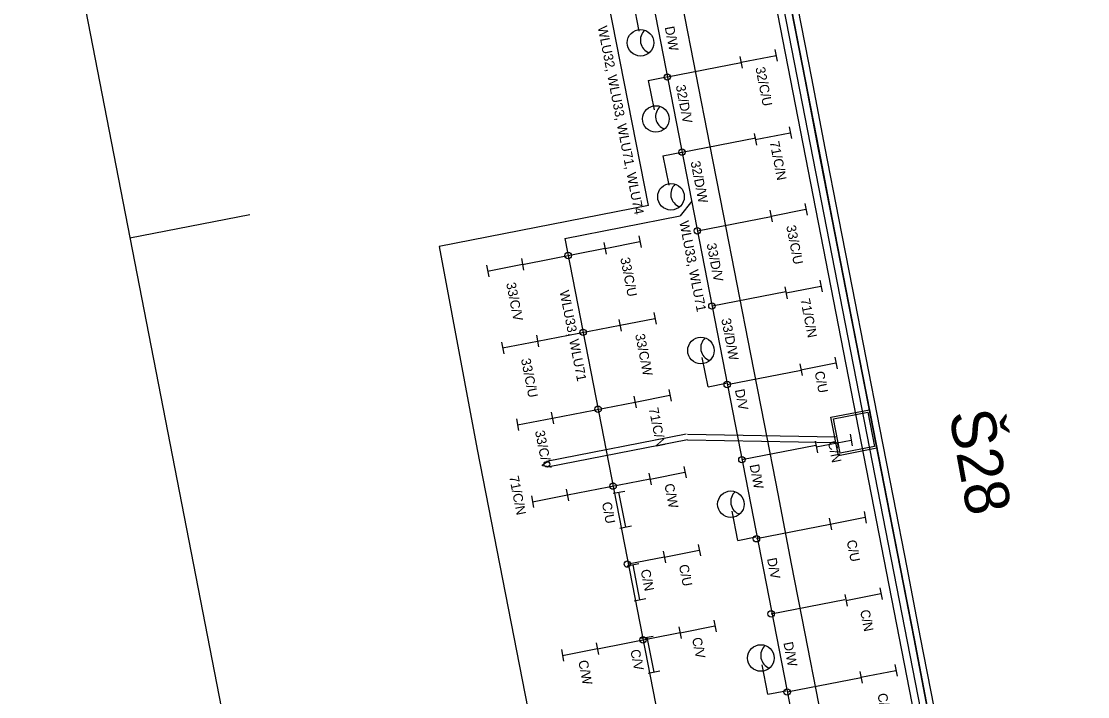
# Model space of a CAD drawing. Extents: x -545258 to -544992, y -1122311 to -1121664.
# Drawn here: x -545221.17 to -545191.21, y -1121911.45 to -1121892.48 of the extents above; entities that cross this region are included whole.
import ezdxf

# ---------------------------------------------------------------- set-up
doc = ezdxf.new("R2010")
doc.units = 0
for name, color, linetype in [('SO18-15-04', 7, 'Continuous'), ('SO18-15-08', 7, 'Continuous'), ('SO18-15-08_def', 7, 'Continuous'), ('SO18-16-02', 7, 'Continuous'), ('SO18-16-03', 7, 'Continuous'), ('so180605', 7, 'Continuous'), ('Vrstva 10', 7, 'Continuous')]:
    doc.layers.add(name, color=color, linetype=linetype)

msp = doc.modelspace()

# ---------------------------------------------------------------- linework, layer by layer
at = {"layer": 'SO18-15-04'}
for centre in [(-545203.02, -1121894.044), (-545202.609, -1121896.154), (-545202.178, -1121898.365), (-545205.807, -1121899.057), (-545201.767, -1121900.475), (-545205.387, -1121901.216), (-545201.337, -1121902.681), (-545204.966, -1121903.375), (-545200.925, -1121904.792), (-545204.545, -1121905.535), (-545200.516, -1121907.014), (-545204.143, -1121907.725), (-545200.105, -1121909.124), (-545203.703, -1121909.854), (-545199.653, -1121911.319)]:
    msp.add_circle(centre, 0.09, dxfattribs=at)
at = {"layer": 'SO18-15-08_def'}
for p, q in [((-545198.422, -1121903.602), (-545197.343, -1121903.392)), ((-545198.212, -1121904.682), (-545198.422, -1121903.602)), ((-545198.355, -1121903.647), (-545197.388, -1121903.459)), ((-545197.388, -1121903.459), (-545197.2, -1121904.426)), ((-545197.343, -1121903.392), (-545197.132, -1121904.471)), ((-545198.167, -1121904.614), (-545198.355, -1121903.647)), ((-545202.489, -1121904.076), (-545206.417, -1121904.842)), ((-545202.455, -1121904.073), (-545198.29, -1121904.154)), ((-545202.458, -1121904.233), (-545206.386, -1121904.999)), ((-545202.458, -1121904.233), (-545198.293, -1121904.314)), ((-545197.132, -1121904.471), (-545198.212, -1121904.682)), ((-545197.2, -1121904.426), (-545198.167, -1121904.614))]:
    msp.add_line(p, q, dxfattribs=at)
for points in [[(-545216.425, -1121805.557), (-545199.926, -1121890.192), (-545199.543, -1121892.155), (-545199.161, -1121894.118), (-545198.778, -1121896.081), (-545198.395, -1121898.044), (-545198.013, -1121900.008), (-545197.63, -1121901.971), (-545197.247, -1121903.934), (-545196.865, -1121905.897), (-545196.482, -1121907.86), (-545196.099, -1121909.823), (-545195.717, -1121911.786), (-545195.334, -1121913.749), (-545194.951, -1121915.712), (-545194.569, -1121917.675), (-545194.186, -1121919.638), (-545193.803, -1121921.601), (-545193.421, -1121923.564), (-545193.038, -1121925.527), (-545192.841, -1121926.538), (-545192.841, -1121926.538)], [(-545206.25, -1121859.831), (-545193.813, -1121923.641), (-545193.431, -1121925.604), (-545193.234, -1121926.608)]]:
    msp.add_lwpolyline(points, dxfattribs=at)
msp.add_circle((-545206.404, -1121904.922), 0.08, dxfattribs=at)
at = {"layer": 'SO18-16-02'}
for points in [[(-545203.55, -1121897.655), (-545204.006, -1121895.32), (-545211.097, -1121859.276), (-545210.828, -1121859.191), (-545213.136, -1121847.58), (-545213.447, -1121847.636), (-545218.7, -1121820.501), (-545218.434, -1121820.401), (-545220.002, -1121812.223), (-545220.322, -1121812.224), (-545225.746, -1121784.731), (-545225.44, -1121784.622), (-545227.044, -1121776.44), (-545227.334, -1121776.447), (-545232.615, -1121749.298), (-545232.32, -1121749.236), (-545234.53, -1121737.665), (-545234.868, -1121737.675), (-545236.659, -1121728.803)], [(-545191.871, -1121931.413), (-545192.253, -1121929.45), (-545192.636, -1121927.486), (-545193.019, -1121925.523), (-545193.401, -1121923.56), (-545193.784, -1121921.597), (-545194.167, -1121919.634), (-545194.549, -1121917.671), (-545194.932, -1121915.708), (-545195.315, -1121913.745), (-545195.697, -1121911.782), (-545196.08, -1121909.819), (-545196.462, -1121907.856), (-545196.845, -1121905.893), (-545197.228, -1121903.93), (-545197.61, -1121901.967), (-545197.993, -1121900.004), (-545198.376, -1121898.041), (-545198.758, -1121896.078), (-545199.141, -1121894.115), (-545199.524, -1121892.152), (-545199.906, -1121890.189), (-545201.881, -1121880.06)], [(-545191.694, -1121931.378), (-545192.077, -1121929.415), (-545192.459, -1121927.452), (-545192.842, -1121925.489), (-545193.225, -1121923.526), (-545193.607, -1121921.563), (-545193.99, -1121919.6), (-545194.372, -1121917.637), (-545194.755, -1121915.674), (-545195.138, -1121913.711), (-545195.52, -1121911.748), (-545195.903, -1121909.785), (-545196.286, -1121907.822), (-545196.668, -1121905.858), (-545197.051, -1121903.895), (-545197.434, -1121901.932), (-545197.816, -1121899.969), (-545198.199, -1121898.006), (-545198.582, -1121896.043), (-545198.964, -1121894.08), (-545199.347, -1121892.117), (-545199.73, -1121890.154), (-545201.704, -1121880.026)], [(-545202.599, -1121892.01), (-545202.216, -1121893.972), (-545201.833, -1121895.936), (-545201.451, -1121897.898), (-545201.068, -1121899.862), (-545200.685, -1121901.825), (-545200.303, -1121903.788), (-545199.92, -1121905.751), (-545199.537, -1121907.714), (-545199.155, -1121909.677), (-545198.772, -1121911.64), (-545198.389, -1121913.603), (-545198.007, -1121915.566), (-545197.624, -1121917.529), (-545197.241, -1121919.492), (-545196.859, -1121921.455), (-545196.476, -1121923.418), (-545196.093, -1121925.381), (-545195.711, -1121927.344), (-545195.328, -1121929.307), (-545194.945, -1121931.27)]]:
    msp.add_lwpolyline(points, dxfattribs=at)
at = {"layer": 'SO18-16-03'}
msp.add_lwpolyline([(-545203.55, -1121897.655), (-545209.426, -1121898.809), (-545208.358, -1121904.507), (-545203.934, -1121927.17), (-545203.066, -1121927.008), (-545201.304, -1121935.983), (-545201.844, -1121936.082), (-545196.986, -1121960.894)], dxfattribs=at)
at = {"layer": 'so180605'}
for p, q in [((-545203.983, -1121891.937), (-545203.823, -1121892.759)), ((-545200.949, -1121893.63), (-545199.967, -1121893.439)), ((-545199.998, -1121893.276), (-545199.934, -1121893.601)), ((-545200.98, -1121893.464), (-545200.916, -1121893.793)), ((-545203.554, -1121894.14), (-545203.394, -1121894.962)), ((-545199.598, -1121895.446), (-545199.535, -1121895.772)), ((-545200.58, -1121895.635), (-545200.516, -1121895.963)), ((-545200.549, -1121895.801), (-545199.568, -1121895.609)), ((-545203.142, -1121896.256), (-545202.981, -1121897.078)), ((-545199.155, -1121897.597), (-545199.092, -1121897.923)), ((-545200.137, -1121897.785), (-545200.073, -1121898.114)), ((-545200.106, -1121897.952), (-545199.125, -1121897.76)), ((-545203.818, -1121898.503), (-545203.754, -1121898.829)), ((-545204.8, -1121898.692), (-545204.736, -1121899.02)), ((-545204.769, -1121898.858), (-545203.788, -1121898.666)), ((-545208.103, -1121899.329), (-545208.039, -1121899.657)), ((-545208.072, -1121899.495), (-545207.09, -1121899.303)), ((-545207.121, -1121899.14), (-545207.057, -1121899.466)), ((-545199.717, -1121899.942), (-545199.653, -1121900.271)), ((-545199.686, -1121900.108), (-545198.704, -1121899.917)), ((-545198.735, -1121899.754), (-545198.671, -1121900.079)), ((-545204.379, -1121900.851), (-545204.315, -1121901.179)), ((-545204.348, -1121901.017), (-545203.367, -1121900.826)), ((-545203.397, -1121900.662), (-545203.334, -1121900.988)), ((-545207.682, -1121901.488), (-545207.618, -1121901.816)), ((-545207.651, -1121901.654), (-545206.67, -1121901.463)), ((-545206.7, -1121901.299), (-545206.636, -1121901.625)), ((-545201.877, -1121902.744), (-545202.037, -1121901.922)), ((-545199.296, -1121902.102), (-545199.232, -1121902.43)), ((-545199.265, -1121902.268), (-545198.283, -1121902.076)), ((-545198.314, -1121901.913), (-545198.25, -1121902.239)), ((-545203.958, -1121903.01), (-545203.894, -1121903.339)), ((-545203.927, -1121903.177), (-545202.946, -1121902.985)), ((-545202.976, -1121902.822), (-545202.913, -1121903.148)), ((-545207.23, -1121903.813), (-545206.249, -1121903.622)), ((-545206.279, -1121903.459), (-545206.216, -1121903.784)), ((-545207.261, -1121903.647), (-545207.197, -1121903.976)), ((-545197.886, -1121904.079), (-545197.823, -1121904.405)), ((-545198.868, -1121904.268), (-545198.804, -1121904.596)), ((-545198.837, -1121904.434), (-545197.856, -1121904.242)), ((-545202.555, -1121904.981), (-545202.492, -1121905.307)), ((-545203.537, -1121905.17), (-545203.473, -1121905.498)), ((-545203.506, -1121905.336), (-545202.525, -1121905.145)), ((-545205.858, -1121905.618), (-545205.795, -1121905.944)), ((-545204.542, -1121905.737), (-545204.216, -1121905.674)), ((-545204.187, -1121906.688), (-545204.378, -1121905.707)), ((-545206.84, -1121905.807), (-545206.776, -1121906.135)), ((-545206.809, -1121905.973), (-545205.828, -1121905.781)), ((-545201.035, -1121907.063), (-545201.195, -1121906.24)), ((-545197.493, -1121906.246), (-545197.43, -1121906.571)), ((-545198.475, -1121906.434), (-545198.411, -1121906.763)), ((-545198.445, -1121906.6), (-545197.463, -1121906.409)), ((-545204.353, -1121906.719), (-545204.024, -1121906.655)), ((-545202.153, -1121907.172), (-545202.09, -1121907.497)), ((-545203.135, -1121907.36), (-545203.071, -1121907.689)), ((-545203.105, -1121907.526), (-545202.123, -1121907.335)), ((-545204.144, -1121907.775), (-545203.818, -1121907.712)), ((-545203.789, -1121908.726), (-545203.981, -1121907.745)), ((-545197.051, -1121908.391), (-545196.988, -1121908.717)), ((-545203.956, -1121908.757), (-545203.627, -1121908.693)), ((-545198.033, -1121908.58), (-545197.969, -1121908.908)), ((-545198.002, -1121908.746), (-545197.021, -1121908.554)), ((-545201.713, -1121909.3), (-545201.65, -1121909.626)), ((-545202.695, -1121909.488), (-545202.631, -1121909.817)), ((-545202.664, -1121909.655), (-545201.683, -1121909.463)), ((-545203.747, -1121909.81), (-545203.421, -1121909.747)), ((-545203.392, -1121910.761), (-545203.584, -1121909.78)), ((-545205.998, -1121910.125), (-545205.934, -1121910.454)), ((-545205.967, -1121910.292), (-545204.986, -1121910.1)), ((-545205.016, -1121909.937), (-545204.953, -1121910.263)), ((-545203.558, -1121910.792), (-545203.23, -1121910.728)), ((-545200.193, -1121911.381), (-545200.354, -1121910.559)), ((-545197.612, -1121910.739), (-545197.548, -1121911.067)), ((-545197.581, -1121910.905), (-545196.6, -1121910.714)), ((-545196.63, -1121910.55), (-545196.567, -1121910.876))]:
    msp.add_line(p, q, dxfattribs=at)
for points in [[(-545218.967, -1121793.701), (-545192.123, -1121931.201)], [(-545220.129, -1121806.302), (-545192.512, -1121947.942)], [(-545203.018, -1121894.041), (-545200.946, -1121893.638)], [(-545203.554, -1121894.14), (-545203.048, -1121894.042)], [(-545202.607, -1121896.151), (-545200.534, -1121895.748)], [(-545203.142, -1121896.256), (-545202.61, -1121896.152)], [(-545202.333, -1121897.532), (-545202.66, -1121897.946)], [(-545205.901, -1121898.577), (-545202.66, -1121897.946)], [(-545202.176, -1121898.362), (-545200.104, -1121897.959)], [(-545205.901, -1121898.577), (-545195.283, -1121953.035)], [(-545207.089, -1121899.306), (-545204.768, -1121898.854)], [(-545201.765, -1121900.473), (-545199.692, -1121900.069)], [(-545206.668, -1121901.465), (-545204.347, -1121901.014)], [(-545201.335, -1121902.678), (-545199.262, -1121902.275)], [(-545201.877, -1121902.744), (-545201.371, -1121902.645)], [(-545206.247, -1121903.625), (-545203.926, -1121903.173)], [(-545200.923, -1121904.789), (-545198.851, -1121904.385)], [(-545205.826, -1121905.784), (-545203.506, -1121905.332)], [(-545200.514, -1121907.011), (-545198.442, -1121906.608)], [(-545201.035, -1121907.063), (-545200.529, -1121906.964)], [(-545204.118, -1121907.72), (-545203.104, -1121907.523)], [(-545200.103, -1121909.121), (-545198.03, -1121908.718)], [(-545204.984, -1121910.103), (-545202.664, -1121909.651)], [(-545199.651, -1121911.316), (-545197.578, -1121910.912)], [(-545200.193, -1121911.381), (-545199.687, -1121911.283)]]:
    msp.add_lwpolyline(points, dxfattribs=at)
for centre in [(-545203.772, -1121893.082), (-545203.343, -1121895.223), (-545202.917, -1121897.407), (-545202.075, -1121901.726), (-545201.234, -1121906.044), (-545200.392, -1121910.363)]:
    msp.add_circle(centre, 0.373, dxfattribs=at)
for centre in [(-545203.405, -1121893.011), (-545202.976, -1121895.152), (-545202.551, -1121897.335), (-545201.709, -1121901.654), (-545200.867, -1121905.973), (-545200.025, -1121910.292)]:
    msp.add_arc(centre, 0.373, 131.0281, 251.0281, dxfattribs=at)
at = {"layer": 'Vrstva 10'}
for p, q in [((-545258.291, -1121692.439), (-545137.778, -1122310.805)), ((-545218.12, -1121898.561), (-545214.752, -1121897.905))]:
    msp.add_line(p, q, dxfattribs=at)

# ---------------------------------------------------------------- texts
at = {"layer": 'SO18-15-08'}
for s, p in [('WLU32, WLU33, WLU71, WLU74', (-545204.978, -1121892.637)), ('D/W', (-545203.095, -1121892.646)), ('32/C/U', (-545200.547, -1121893.786)), ('32/D/V', (-545202.785, -1121894.288)), ('71/C/N', (-545200.146, -1121895.869)), ('32/D/W', (-545202.368, -1121896.428)), ('WLU33, WLU71', (-545202.686, -1121898.111)), ('33/C/U', (-545199.681, -1121898.232)), ('33/D/V', (-545201.918, -1121898.734)), ('33/C/U', (-545204.343, -1121899.138)), ('33/C/V', (-545207.549, -1121899.838)), ('WLU33, WLU71', (-545206.049, -1121900.063)), ('71/C/N', (-545199.284, -1121900.291)), ('33/D/W', (-545201.507, -1121900.846)), ('33/C/W', (-545203.926, -1121901.279)), ('33/C/U', (-545207.133, -1121901.971)), ('C/U', (-545198.885, -1121902.332)), ('D/V', (-545201.123, -1121902.834)), ('71/C/N', (-545203.542, -1121903.355)), ('33/C/V', (-545206.739, -1121903.994)), ('C/N', (-545198.508, -1121904.291)), ('D/W', (-545200.711, -1121904.946)), ('71/C/N', (-545207.466, -1121905.271)), ('C/W', (-545203.105, -1121905.49)), ('C/U', (-545204.861, -1121906.004)), ('C/U', (-545197.983, -1121907.073)), ('C/U', (-545202.697, -1121907.761)), ('D/V', (-545200.221, -1121907.575)), ('C/N', (-545203.771, -1121907.897)), ('C/N', (-545197.606, -1121909.032)), ('C/V', (-545202.327, -1121909.809)), ('D/W', (-545199.761, -1121909.936)), ('C/V', (-545204.061, -1121910.146)), ('C/W', (-545205.524, -1121910.449)), ('C/U', (-545197.12, -1121911.378))]:
    msp.add_text(s, height=0.2688, rotation=281.121, dxfattribs=at).set_placement(p)
at = {"layer": 'SO18-15-08_def'}
msp.add_text('Š28', height=1.25, rotation=280.4462, dxfattribs=at).set_placement((-545195.111, -1121903.493))

doc.saveas('drawing.dxf')
